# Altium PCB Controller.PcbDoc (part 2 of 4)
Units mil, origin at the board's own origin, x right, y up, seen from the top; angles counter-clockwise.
Board outline 5000 x 8750 mil, 6 copper layers (Top Layer, Layer 1, Layer 2, Layer 3, Layer 4, Bottom Layer), stack 92.6 mil thick; 303 components, 258 nets, 1062 pads, 274 vias.
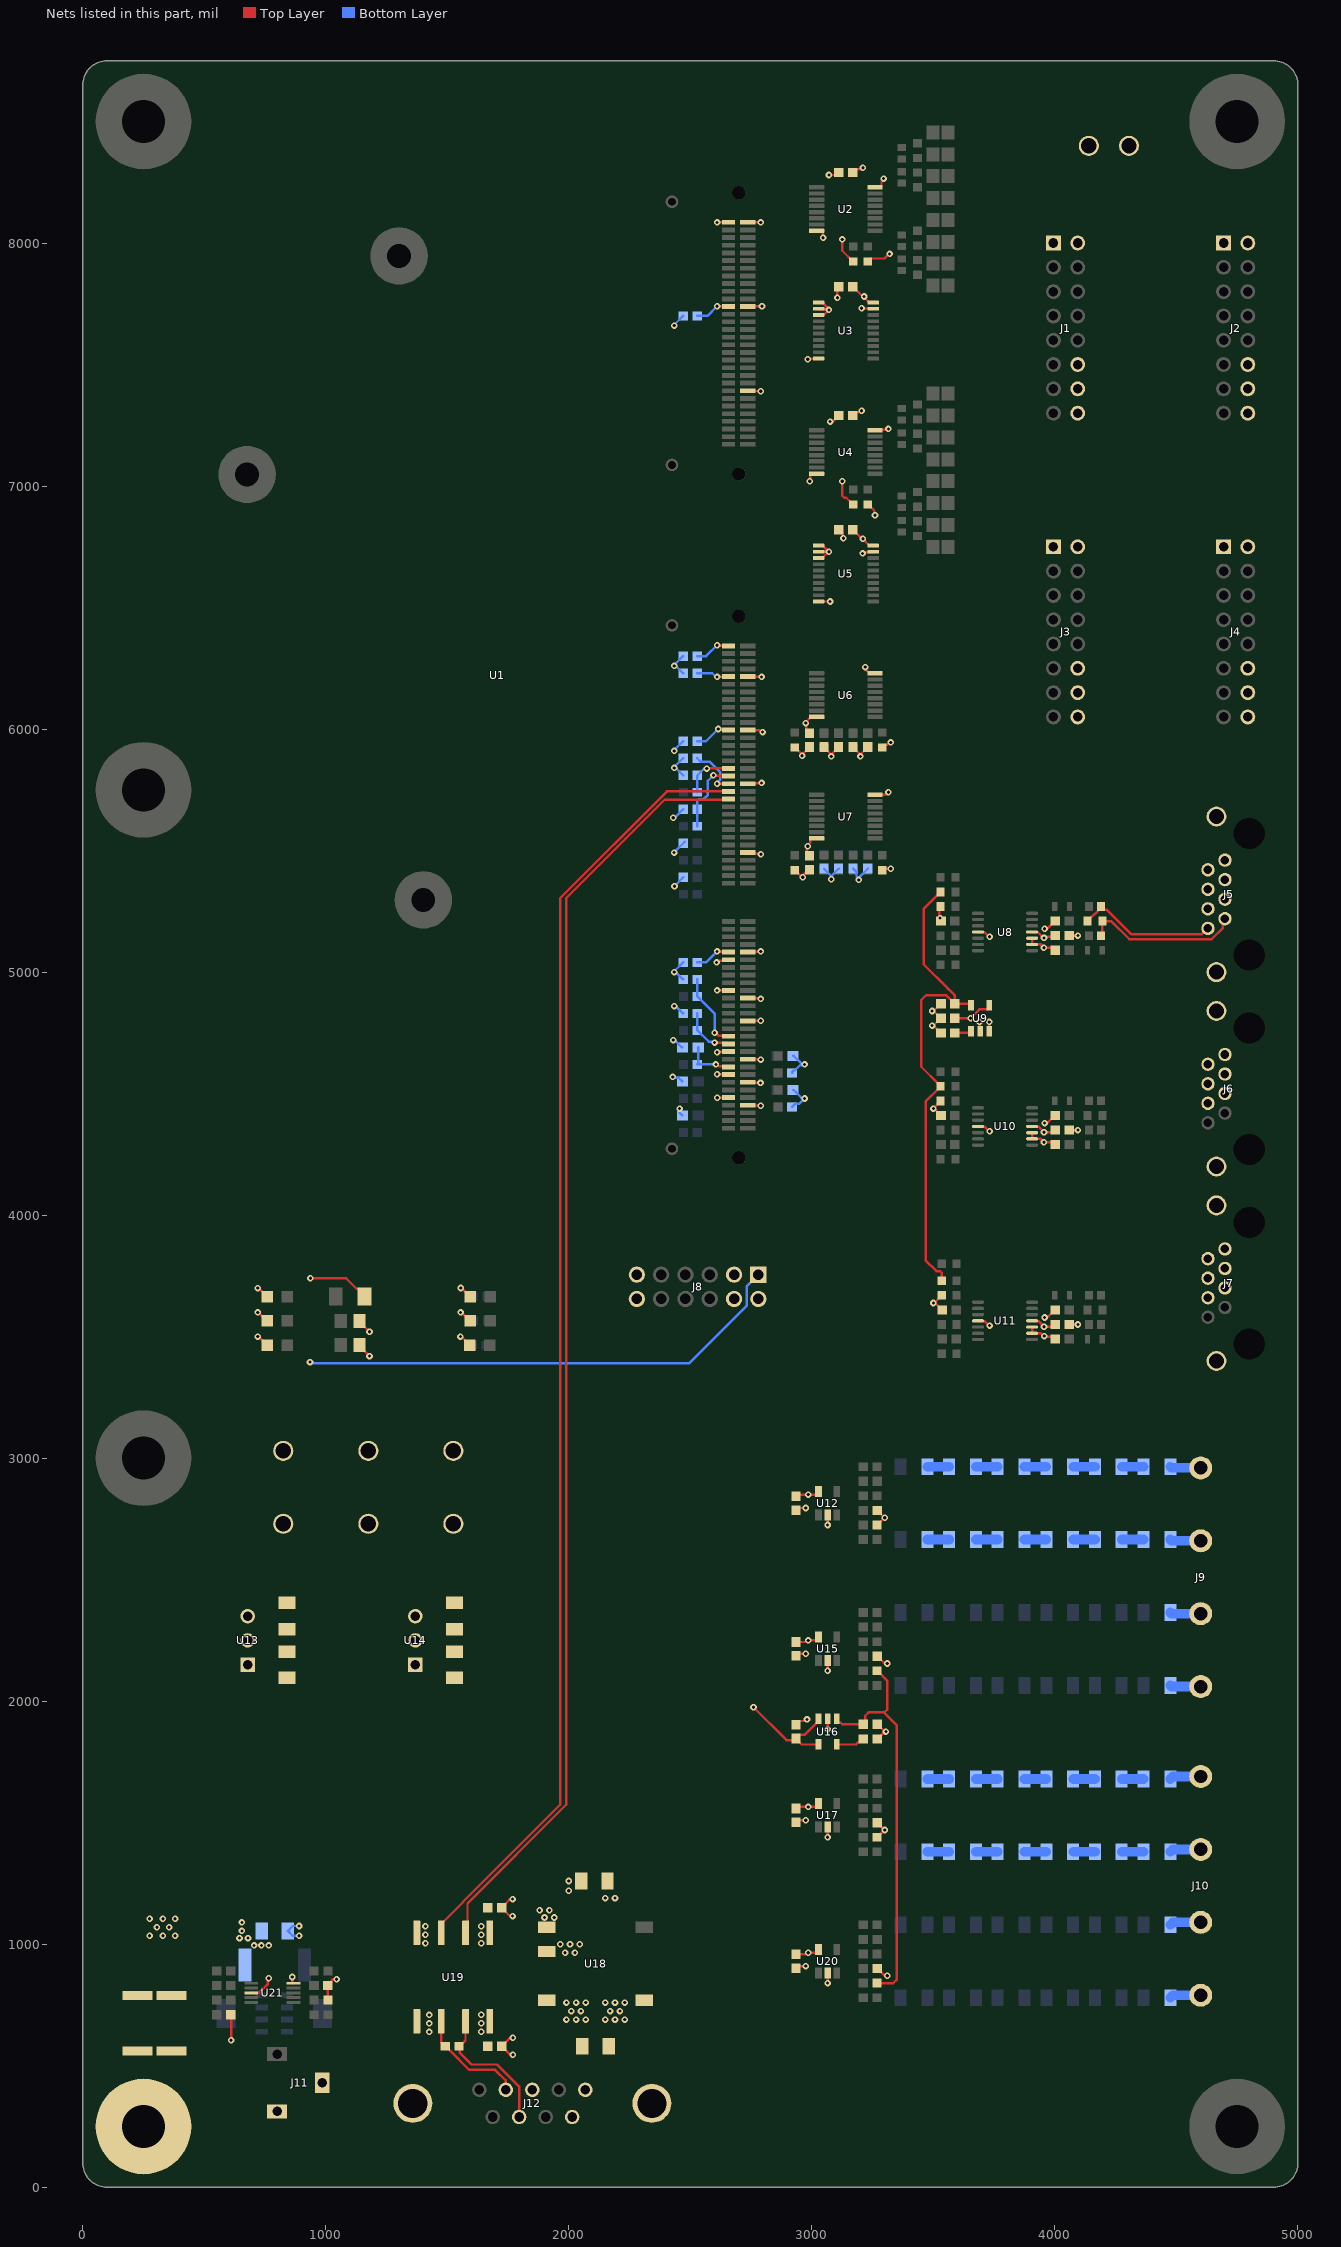
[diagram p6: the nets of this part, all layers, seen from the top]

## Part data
C1 C3 C4 C5 C7 C9 C10 C11: library part CMP-03020-017376-1, "CAP CER 27PF 250V C0G/NP0 0603", Capacitance="27 pF", Case/Package=0603, Manufacturer=KEMET, Package=CBR06C, Temperature="-55°C to +125°C", Temperature Characteristic=C0G, Temperature Coefficient=30ppm/°C, Temperature Range High=+125°C, Temperature Range Low=-55°C, Tolerance=0.01, Voltage Rating=250V
C2 C6 C8 C12 C13 C18 C21 C24 C25 C26 C29 C34 C38 C43 C47 C48 C49 C51 C54 C56 C61 C62 C63 C64 C65 C66 C75: library part CMP-2006-03057-2, "CAP CER 0.1UF 25V X7R 0603", Capacitance=0.10μF, Case/Package=0603, Manufacturer=KEMET, Temperature="-55°C to +125°C", Temperature Characteristic=X7R, Temperature Coefficient=30ppm/°C, Temperature Range High=+125°C, Temperature Range Low=-55°C, Tolerance=0.1, Voltage Rating=25V
C14 C15 C16 C17 C19 C20 C22 C23 C27 C28 C30 C31 C32 C33 C35 C36 C42 C46 C55 C57 C70 C71 C72 C73: library part CMP-001-00096-9, "CAP CER 100PF 50V X7R 0603", Capacitor Type=Ceramic, Case/Package=0603, Manufacturer=YAGEO, Max Operating Temperature=125°C, Min Operating Temperature=-55°C, Temperature Coefficient=X7R, Tolerance=10%, Voltage Rating=50V
C37 C39 C50 C52 C59: "CAP CER 4700PF 25V 10% X7R 0603", Capacitance=4.7nF, Case Code (Imperial)=0603, Case Code (Metric)=1608, Dielectric=X7R, Dielectric Material=Ceramic, Manufacturer=KEMET, Manufacturer Part Number=C0603C472K3RACTU, Max Operating Temperature=125°C, Min Operating Temperature=-55°C, Package Quantity=1, Supplier Part Number 1=67AH9250, Tolerance=10%, Voltage Rating=25V
C40 C41 C44 C45 C53 C60 C85: library part CMP-13271-001434-1, "CAP CER 10UF 25V X7R 1206", Capacitance=10μF, Case Code (Imperial)=1206, Case Code (Metric)=3216, Dielectric=X7R, Manufacturer=SAMSUNG, Max Operating Temperature=125°C, Min Operating Temperature=-55°C, Package Quantity=1, Tolerance=10%, Voltage Rating=25V
C58: "CAP CER 0.022UF 50V X7R 0805", Capacitance=22nF, Case Code (Imperial)=0805, Case Code (Metric)=2012, Dielectric=X7R, Dielectric Material=Ceramic, Insulation Resistance=100GR, Manufacturer=YAGEO, Max Operating Temperature=125°C, Min Operating Temperature=-55°C, Package Quantity=1, Supplier Part Number 1=2104784, Tolerance=10%, Voltage=50V
C67 C68 C69 C74 C76 C77: "CAP CER 56PF 50V C0G/NP0 0603", Capacitance=56pF, Case Code (Imperial)=0603, Case Code (Metric)=1608, Dielectric=C0G, Manufacturer=SAMSUNG, Max Operating Temperature=125°C, Min Operating Temperature=-55°C, Package Quantity=1, Temperature Coefficient=30ppm/°C, Tolerance=5%, Voltage=50V
C78 C79 C81 C82 C84: library part CMP-06035-043171-1, "CAP CER 0.27UF 16V X7R 0603", Capacitance=0.27μF, Case/Package=0603, Dielectric=X7R, Manufacturer=MURATA, Tolerance=10%, Voltage Rating (DC)=16V
C80 C83: library part CMP-001-00098-12, "CAP CER 1000PF 50V C0G/NP0 0603", Capacitor Type=Ceramic, Case/Package=0603, Manufacturer=KEMET, Manufacturer Part Number=C0603C102G5GAC7867, Max Operating Temperature=125°C, Min Operating Temperature=-55°C, Temperature Coefficient=C0G, Tolerance=2%, Voltage Rating=50V
D1 D2 D3 D5: library part CMP-22017-000007-1, "LED GREEN CLEAR CHIP SMD", Case Code (Imperial)=0805, Case Code (Metric)=2012, Color=GREEN, Forward Current=30mA, Forward Voltage=2.1V, Illumination Color=Green, Lens Color=Colorless, Manufacturer=LITE-ON, Max Operating Temperature=85°C, Min Operating Temperature=-55°C, Package Quantity=1, Power Dissipation=100mW, Reverse Voltage=5V, Test Current=10mA
D4: "LED YELLOW CLEAR 0805 SMD", Case Code (Imperial)=0805, Case Code (Metric)=2012, Color=Yellow, Forward Current=30mA, Forward Voltage=2V, Lens Color=Colorless, Manufacturer=LITE-ON, Max Operating Temperature=85°C, Max Power Dissipation=75mW, Min Operating Temperature=-55°C, Package Quantity=1, Reverse Voltage=5V, Supplier Part Number 1=6920950, Test Current=20mA
D6: "LED RED DIFFUSED 0805 SMD", Case Code (Imperial)=0805, Case Code (Metric)=2012, Color=RED, Forward Current=20mA, Forward Voltage=2V, Illumination Color=Red, Manufacturer="VISUAL COMMUNICATIONS", Max Operating Temperature=85°C, Min Operating Temperature=-40°C, Package Quantity=1, Power Rating=100mW, Reverse Voltage=5V, Supplier Part Number 1=45X6246
J1 J2 J3 J4: "CONN HEADER VERT 16POS 2.54MM", Case/Package=N/A, Flammability Rating="UL94 V-0", Insulation Color=Black, Manufacturer=SULLINS, Max Operating Temperature=105°C, Min Operating Temperature=-40°C, Supplier Part Number 1=S9171-ND
J5 J6 J7: "CONN MOD JACK R/A 8P8C SHLD", Case/Package=N/A, Manufacturer=TE
J8: "CONN HEADER VERT 12POS 2.54MM", Case/Package=N/A, Color=Black, Flammability Rating="UL94 V-0", Manufacturer="WURTH ELEKTRONIK", Manufacturer Print=WURTH, Max Operating Temperature=105°C, Min Operating Temperature=-40°C, Supplier Part Number 1=732-5297-ND, Voltage Rating=250V
J9 J10: "TERM BLOCK HDR 4POS 90DEG 7.62MM", Case/Package=N/A, Manufacturer="PHOENIX CONTACT"
J11: "CONN PWR JACK 2X5.5MM SOLDER", Case/Package=N/A, Color=Black, Current Rating=5A, Flammability Rating="UL94 V-0", Insulation Resistance=50MR, Manufacturer=CUI, Manufacturer Print="CUI DEVICES", Max Operating Temperature=85°C, Min Operating Temperature=-25°C, Package Quantity=280, Voltage Rating=24V
J12: "CONN D-SUB PLUG 9POS R/A SLDR", Case/Package=N/A, Color=Black, Current Rating=5A, Manufacturer=AMPHENOL, Max Operating Temperature=155°C, Max Supply Voltage (AC)=250V, Min Operating Temperature=-55°C, Supplier Part Number 1=70145033
L1 L2 L3 L4 L5 L6 L7 L8 L9 L10 L11 L12 L13 L14 L15 L16: library part CMP-08253-000143-1, "FIXED IND 1UH 1.15A 60 MOHM SMD", Case Code (Imperial)=0805, Case Code (Metric)=2012, Current Rating=1.15A, DC Resistance (DCR)=78mR, Inductance=1uH, Manufacturer=TDK, Max Operating Temperature=125°C, Min Operating Temperature=-55°C, Package Quantity=1, Saturation Current=220mA, Self Resonant Frequency=160MHz, Test Frequency=2MHz, Tolerance=20%
Q1 Q2: "MOSFET N-CH 120V 90A PWRDI5060-8", Case/Package=8-PowerTDFN, Manufacturer="DIODES INC", Supplier Part Number 1=68AH9585
R1 R2 R3 R6 R7 R8 R11 R12: library part CMP-009-00005-4, "RES 100 OHM 1% 1/10W 0603", Case/Package=0603, Manufacturer=YAGEO, Manufacturer Part Number=RC0603FR-13100RL, Max Operating Temperature=155°C, Min Operating Temperature=-55°C, Power=0.1W, Tolerance=1%, Voltage Rating=75V
R4 R5 R9 R10 R13 R14 R15 R20: library part CMP-009-00107-4, "RES SMD 15K OHM 0.1% 1/10W 0603", Case/Package=0603, Manufacturer=YAGEO, Max Operating Temperature=155°C, Min Operating Temperature=-55°C, Power=0.1W, Tolerance=0.1%, Voltage Rating=75V
R16 R17 R18 R19 R26 R40 R51 R83 R84 R85 R86: library part CMP-009-00006-5, "RES 120 OHM 1% 1/10W 0603", Case/Package=0603, Manufacturer=YAGEO, Max Operating Temperature=155°C, Min Operating Temperature=-55°C, Power=0.1W, Tolerance=1%, Voltage Rating=75V
R21 R28 R33 R42 R45 R54: library part CMP-009-00218-2, "RES SMD 27K OHM 0.5% 1/16W 0603", Case/Package=0603, Manufacturer=SUSUMU, Max Operating Temperature=125°C, Min Operating Temperature=-55°C, Power=0.06W, Tolerance=0.5%, Voltage Rating=75V
R22 R24 R34 R37 R46 R49: library part CMP-009-00039-5, "RES 20K OHM 1% 1/10W 0603", Case/Package=0603, Manufacturer=STACKPOLE, Max Operating Temperature=155°C, Min Operating Temperature=-55°C, Power=100mW, Tolerance=1%, Voltage Rating=75V
R23 R27 R36 R41 R48 R53: library part CMP-2000-02579-2, "RES SMD 2.7K OHM 0.5% 1/16W 0603", Case Code (Imperial)=0603, Case Code (Metric)=1608, Manufacturer=SUSUMU, Max Operating Temperature=125°C, Max Power Dissipation=63mW, Min Operating Temperature=-55°C, Package Quantity=1, Power Rating=62.5mW, Resistor Type="Thin Film", Temperature Coefficient=25ppm/°C, Tolerance=0.5%, Voltage Rating=75V
R25 R29 R38 R43 R50 R55: library part CMP-009-00255-1, "RES SMD 1K OHM 0.05% 1/10W 0603", Case/Package=0603, Manufacturer=PANASONIC, Max Operating Temperature=155°C, Min Operating Temperature=-55°C, Power=100mW, Temperature Coefficient=10ppm/°C, Tolerance=0.05%, Voltage Rating=75V
R30 R44 R57: library part CMP-009-00206-2, "RES SMD 10K OHM 0.1% 1/10W 0603", Case/Package=0603, Manufacturer=SUSUMU, Manufacturer Part Number=RG1608P-103-B-T5, Max Operating Temperature=155°C, Min Operating Temperature=-55°C, Power=100mW, Tolerance=0.1%, Voltage Rating=75V
R31 R32 R35 R39 R93 R94 R95: "RES SMD 49.9 OHM 1% 1/10W 0603", Case Code (Imperial)=0603, Case Code (Metric)=1608, Manufacturer=PANASONIC, Max Operating Temperature=155°C, Max Power Dissipation=100mW, Min Operating Temperature=-55°C, Package Quantity=5000, Power Rating=0.1W, Resistance=49.9Ω, Resistance Tolerance=1%, Resistor Type="Thick Film", Supplier Part Number 1=12AC1058, Temperature Coefficient=100ppm/°C, Voltage Rating=75V, Voltage Rating (DC)=50V, Working Voltage=6V
R47: "RES 249 OHM 1% 1/4W 1206", Case Code (Imperial)=1206, Case Code (Metric)=3216, Manufacturer=YAGEO, Max Operating Temperature=155°C, Max Power Dissipation=250mW, Min Operating Temperature=-55°C, Power Rating=0.25W, Resistance=249Ω, Resistor Type="Thick Film", Supplier Part Number 1=1142064, Temperature Coefficient=100ppm/°C, Tolerance=1%, Voltage Rating=200V
R52: "RES 499 OHM 1% 1/8W 0805", Case Code (Imperial)=0805, Case Code (Metric)=2012, Manufacturer=YAGEO, Max Operating Temperature=155°C, Max Power Dissipation=0.13W, Min Operating Temperature=-55°C, Package Quantity=1, Power Rating=125mW, Resistance=499Ω, Resistor Type="Thick Film", Supplier Part Number 1=5825161, Temperature Coefficient=100ppm/°C, Tolerance=1%, Voltage Rating=150V
R56: "RES SMD 2.43K OHM 1% 1/8W 0805", Case Code (Imperial)=0805, Case Code (Metric)=2012, Manufacturer=PANASONIC, Max Operating Temperature=155°C, Max Power Dissipation=125mW, Min Operating Temperature=-55°C, Package Quantity=1, Power Rating=0.13W, Resistance=2.43kΩ, Resistance Tolerance=1%, Resistor Type="Thick Film", Supplier Part Number 1=73AC7648, Temperature Coefficient=100ppm/°C, Voltage Rating=150V
R58 R61 R62 R65 R66 R69 R70 R76: "RES 4.99K OHM 1% 1/10W 0603", Case Code (Imperial)=0603, Case Code (Metric)=1608, Manufacturer=YAGEO, Max Operating Temperature=155°C, Max Power Dissipation=0.1W, Min Operating Temperature=-55°C, Package Quantity=1, Resistance=4.99kΩ, Resistance Tolerance=1%, Resistor Type="Thick Film", Supplier Part Number 1=1995595, Temperature Coefficient=100ppm/°C, Voltage Rating=75V, Voltage Rating (DC)=50V
R59 R60 R67 R68: "RES SMD 3.74K OHM 0.1% 1/5W 0603", Case Code (Imperial)=0603, Case Code (Metric)=1608, Manufacturer=PANASONIC, Max Operating Temperature=155°C, Max Power Dissipation=0.2W, Min Operating Temperature=-55°C, Resistance=3.74kΩ, Resistor Type="Thick Film", Temperature Coefficient=50ppm/°C, Tolerance=0.1%
R63 R64 R71 R74: "RES SMD 1.8K OHM 0.1% 1/5W 0603", Case Code (Imperial)=0603, Case Code (Metric)=1608, Manufacturer=PANASONIC, Max Operating Temperature=155°C, Max Power Dissipation=0.2W, Min Operating Temperature=-55°C, Resistance=1.8kΩ, Resistor Type="Thick Film", Temperature Coefficient=50ppm/°C, Tolerance=0.1%
R72 R73: "RES 2.7M OHM 5% 1/10W 0603", Case Code (Imperial)=0603, Case Code (Metric)=1608, Manufacturer=YAGEO, Max Operating Temperature=155°C, Max Power Dissipation=100mW, Min Operating Temperature=-55°C, Package Quantity=1, Power Rating=0.1W, Resistance=2.7MΩ, Resistor Type="Thick Film", Temperature Coefficient=100ppm/°C, Tolerance=5%, Voltage Rating=75V, Voltage Rating (DC)=50V
R75 R81: "RES 100K OHM 1% 1/10W 0603", Case Code (Imperial)=0603, Case Code (Metric)=1608, Manufacturer=YAGEO, Max Operating Temperature=155°C, Max Power Dissipation=100mW, Min Operating Temperature=-55°C, Power Rating=0.1W, Resistance=100kΩ, Resistance Tolerance=1%, Resistor Type="Thick Film", Supplier Part Number 1=3697448, Temperature Coefficient=100ppm/°C, Voltage Rating=50V, Working Voltage=75V
R77 R78: library part CMP-2000-06974-2, "RES SMD 0 OHM JUMPER 1W 2512", Case Code (Imperial)=2512, Case Code (Metric)=6432, Manufacturer=YAGEO, Max Operating Temperature=155°C, Max Power Dissipation=1W, Min Operating Temperature=-55°C, Package Quantity=4000, Resistance Tolerance=5%, Resistor Type="Thick Film", Temperature Coefficient=200ppm/°C, Voltage Rating=200V
R79: library part CMP-2000-00337-2, "RES SMD 22K OHM 1% 1/10W 0603", Case Code (Imperial)=0603, Case Code (Metric)=1608, Manufacturer=PANASONIC, Max Operating Temperature="155 degC", Min Operating Temperature="-55 degC", Package Quantity=200, Power Rating=0.1W, Resistance=22kΩ, Tolerance=1%, Voltage Rating="50 V"
R80: "RES SMD 200K OHM 1% 1/10W 0603", Case Code (Imperial)=0603, Case Code (Metric)=1608, Manufacturer=PANASONIC, Max Operating Temperature=155°C, Max Power Dissipation=0.1W, Min Operating Temperature=-55°C, Package Quantity=1, Power Rating=100mW, Resistance=200kΩ, Resistance Tolerance=1%, Resistor Type="Thick Film", Supplier Part Number 1=25AC9147, Temperature Coefficient=100ppm/°C, Voltage Rating=75V, Voltage Rating (DC)=50V
R82: "RES SMD 120 OHM 5% 1/10W 0603", Case Code (Imperial)=0603, Case Code (Metric)=1608, Manufacturer=YAGEO, Max Operating Temperature=155°C, Max Power Dissipation=0.1W, Min Operating Temperature=-55°C, Package Quantity=1, Power Rating=100mW, Resistance=120Ω, Resistance Tolerance=5%, Resistor Type="Thick Film", Supplier Part Number 1=2424206, Temperature Coefficient=100ppm/°C, Voltage Rating=50V
R87 R88 R89 R90 R91 R92: "RES SMD 0 OHM JUMPER 1/10W 0603", Case Code (Imperial)=0603, Case Code (Metric)=1608, Manufacturer="VISHAY DALE", Manufacturer Part Number=CRCW06030000Z0EBC, Max Operating Temperature=155°C, Max Power Dissipation=100mW, Min Operating Temperature=-55°C, Package Quantity=10000, Ratings=AEC-Q200, Resistance=0Ω, Resistor Type="Thick Film", Supplier Part Number 1=48P7902, Temperature Coefficient=100ppm/°C, Tolerance=1%, Voltage Rating=75V
R96 R97 R98: "RES 680 OHM 1% 1/10W 0603", Case Code (Imperial)=0603, Case Code (Metric)=1608, Manufacturer=YAGEO, Max Operating Temperature=155°C, Max Power Dissipation=100mW, Min Operating Temperature=-55°C, Package Quantity=1, Power Rating=0.1W, Resistance=680Ω, Resistance Tolerance=1%, Resistor Type="Thick Film", Supplier Part Number 1=6789788, Temperature Coefficient=100ppm/°C, Voltage Rating=50V
R99 R100 R101 R102 R103 R104 R105 R106 R107 R108 R109 R110 R111 R112 R113 R114 R115 R116 R117 R118 R119 R120 R121 R122 R123 R124 R125 R126 R127 R128 R129 R130 R131 R132 R133 R134 R135 R136 R137 R138 R139 R140 R142 R143 R144 R145 R146 R147: library part CMP-2003-04604-1, "RES 249K OHM 0.1% 1/4W 1206", Case/Package=1206, Manufacturer="VISHAY DALE", Power=0.25W, Resistance=249kΩ
R141: "RES 0.01 OHM 1% 2W 2512", Case Code (Imperial)=2512, Case Code (Metric)=6432, Manufacturer=YAGEO, Max Operating Temperature=170°C, Max Power Dissipation=2W, Min Operating Temperature=-55°C, Resistance=10mΩ, Resistor Type="Metal Film", Supplier Part Number 1=1995902P, Temperature Coefficient=50ppm/°C, Tolerance=1%
TP1 TP2 TP6 TP7 TP8: library part CMP-1672-00003-4, "PC TEST POINT MULTIPURPOSE BLACK", Case/Package=N/A, Colour=Black, Manufacturer=KEYSTONE, Package Quantity=100
TP3 TP4 TP5: library part CMP-1672-00002-4, "PC TEST POINT MULTIPURPOSE RED", Case/Package=N/A, Colour=Red, Manufacturer=KEYSTONE, Package Quantity=100
U1: "CONTROLCARD TMS320F28379D EVAL", Case/Package=N/A, Manufacturer="TEXAS INSTRUMENTS", Supplier Part Number 1=595-TMDSCNCD28379D
U2 U4: library part CMP-0310-00537-3, "IC RECEIVER 0/4 16TSSOP", Case/Package=16-TSSOP, Manufacturer="TEXAS INSTRUMENTS", Rating=Catalog, Receivers Per Package=4, Supply Voltage(s)(Max)(V)=3.6, Supply Voltage(s)(Min)(V)=3, Supply Voltage(s)(V)=3.3
U3 U5: library part CMP-0440-01163-3, "IC BUF NON-INVERT 5.5V 20TSSOP", Case/Package=20-TSSOP, F @ Nom Voltage(Max)(Mhz)=110, Generic Part Number=SN74LV541AT, ICC @ Nom Voltage(Max)(mA)=0.02, Manufacturer="TEXAS INSTRUMENTS", Operating Temperature Range(C)="-40 to 125", Rating=Catalog, tpd @ Nom Voltage(Max)(ns)=7.9, Voltage(Nom)(V)=5
U6 U7: library part CMP-0310-00542-2, Case/Package=16-TSSOP, Drivers Per Package=4, Manufacturer="TEXAS INSTRUMENTS", Rating=Catalog, Supply Voltage(s)(Max)(V)=3.6, Supply Voltage(s)(Min)(V)=3, Supply Voltage(s)(V)=3.3
U8 U10 U11: library part CMP-0384-01836-1, "IC CMOS 4 CIRCUIT 14TSSOP", Amplifiers Per Package=4, Case/Package=14-TSSOP, Generic Part Number=AD8618, Input Bias Current=200fA, Input Offset Voltage=23uV, Manufacturer="ANALOG DEVICES"
U9 U16: library part CMP-04916-000006-1, "IC VREF SERIES 1.5V/3V 5SOT", Case/Package=TSOT-23-5, Manufacturer="TEXAS INSTRUMENTS", Max Junction Temp=+150°C, Max Supply Voltage=5.5V, Min Supply Voltage=3V, Nominal Supply Current=360uA, Output Voltage=1.5/3V, Package=DDC0005A, Temperature="-40°C to +125°C", Temperature Range High=+125°C, Temperature Range Low=-40°C
U12 U15 U17 U20: library part CMP-0384-02059-2, "IC OPAMP GP 1 CIRCUIT TSOT23-5", Amplifiers Per Package=1, Case/Package=TSOT-23-5, Generic Part Number=AD8615, Input Bias Current=200fA, Input Offset Voltage=80uV, Manufacturer="ANALOG DEVICES"
U13: "DC DC CONVERTER 3.3V 3W", Case/Package=SIP, Manufacturer=RECOM, Max Input Voltage=28V, Max Operating Temperature=85°C, Max Output Current=1A, Max Output Power=3.3W, Max Output Voltage=3.3V, Max Power Dissipation=3W, Min Input Voltage=8V, Min Input Voltage (DC)=7V, Min Operating Temperature=-40°C, Package=3-SIP, Supplier Part Number 1=9176626
U14: "DC DC CONVERTER 5V 5W", Case/Package=SIP, Current - Output 1=1A, Manufacturer=RECOM, Max Input Voltage=28V, Max Operating Temperature=85°C, Max Output Voltage=5V, Max Power Dissipation=5W, Min Input Voltage=8V, Min Operating Temperature=-40°C, Package=3-SIP, Package Quantity=42, Supplier Part Number 1=1446013
U18: "DC DC CONVERTER 5V 1W", Case/Package=SMD/SMT, Current - Output 1=200mA, Isolation Voltage=2kV, Manufacturer=RECOM, Max Input Voltage=3.63V, Max Operating Temperature=100°C, Max Output Power=1W, Max Output Voltage=5V, Min Input Voltage=2.97V, Min Operating Temperature=-40°C, Package=8-SMD, Supplier Part Number 1=945-R1SE-3.305/H2-RCT-ND
U19: "IC TXRX/ISO HALF 1/1 8SOP", Case/Package=8-SOP, Drivers Per Package=1, Manufacturer="TEXAS INSTRUMENTS", Rating=Catalog
U21: "IC SURGE SUPPRESSION ADJ 10MSOP", Case/Package=10-MSOP, Manufacturer="ANALOG DEVICES", Supplier Part Number 1=505-LTC4368IMS-2#PBF-ND

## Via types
v1: diameter 27, hole 13, Top Layer to Bottom Layer, tented both sides, 274 vias

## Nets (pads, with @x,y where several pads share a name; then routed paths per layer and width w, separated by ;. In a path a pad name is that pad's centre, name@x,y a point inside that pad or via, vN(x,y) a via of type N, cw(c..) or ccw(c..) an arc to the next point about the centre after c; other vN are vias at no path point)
+1.5V_I: C26.1 U9.1 | length 69.5
  Top Layer w10: C26.1@3588.58,4750 3648.39,4750 U9.1@3655.2,4756.81
+1.5V_V: C47.1 R64.2 R74.2 U16.1 | length 1646.7
  Top Layer w10: U16.1@3102.4,1928.15 3102.4,1918.31 3109.21,1911.5 3119.06,1911.5 3125.55,1905 3205.95,1905 3219.81,1918.86 3219.81,1939.81 3235,1955 3295,1955 3350,1900 3350,855 3335,840 R74.2@3268.62,840 ; R64.2@3268.62,2125 3269.53,2125 3310,2084.53 3310,1965 3297.5,1952.5
+3.3V: C2.1 C6.1 C8.1 C12.1 C13.1 C18.1 C38.1 C40.1 C43.1 C51.1 C53.1 C54.1 C56.1 J8.1 R4.2 R9.2 R14.2 R20.2 R47.1 TP3.1 U2.16 U3.20 U4.16 U5.20 U6.16 U7.16 U12.5 U13.3 U15.5 U17.5 U18.2 U19.1 U20.5 | length 3676.5
  Top Layer w10: v1(936.54,3740) 1084.1,3740 1127.52,3696.58 1135.45,3696.58 1159.1,3672.92 R47.1@1159.1,3665 ; C56.1@2935,958.58 2973.98,958.58 2980.4,965 v1(2985,965) 3018.82,965 3027.6,973.78 U20.5@3027.6,978.23 ; C51.1@2935,1558.58 2941.42,1565 v1(2985,1565) 3018.82,1565 3027.6,1573.78 U17.5@3027.6,1578.23 ; C43.1@2935,2243.58 2973.98,2243.58 2980.4,2250 v1(2985,2250) 3018.82,2250 3027.6,2258.78 U15.5@3027.6,2263.23 ; C38.1@2935,2843.58 2941.42,2850 3018.82,2850 3027.6,2858.78 U12.5@3027.6,2863.23 ; v1(2983.41,5518.1) v1@2978.25,5518.1 ; C18.1@2990,5483.58 2978.25,5495.32 v1@2978.25,5518.1 ; C13.1@2990,5983.58 2976.14,5997.44 2976.14,6023.86 2975,6025 2975,6028.15 2997.28,6050.43 U6.16@3019.92,6050.43 ; U7.16@3019.92,5550.43 2997.28,5550.43 2993.43,5546.57 2993.43,5532.72 2978.81,5518.1 v1@2978.25,5518.1 ; v1(3125,7020) 3125,6960 3133.25,6951.75 3141.62,6951.75 3168.95,6924.42 R9.2@3170,6924.42 ; v1(3125,8015) 3125,7968.37 3168.95,7924.42 R4.2@3170,7924.42 ; C12.1@3168.58,6820 3169.53,6820 3206.22,6783.31 v1(3210,6783.31) 3210,6781.61 3236.46,6755.16 U5.20@3252.2,6755.16 ; C8.1@3168.58,7290 3182.44,7303.86 3194.26,7303.86 3200.4,7310 v1(3205,7310) ; C6.1@3168.58,7820 3169.53,7820 3206.27,7783.25 3211.75,7783.25 v1(3215,7780) 3215,7776.61 3236.46,7755.16 U3.20@3252.2,7755.16 ; C2.1@3168.58,8290 3182.44,8303.86 3199.26,8303.86 3205.4,8310 v1(3210,8310) ; U4.16@3260.08,7229.57 3262.8,7232.28 3312.28,7232.28 v1(3315,7235) ; U2.16@3260.08,8229.57 3282.72,8229.57 3286.57,8233.43 3286.57,8251.97 3295,8260.4 v1(3295,8265) ; R20.2@3290,5424.42 3290.58,5425 v1(3325,5425) ; R14.2@3290,5924.42 3301.9,5936.32 3311.42,5936.32 3320.37,5945.27 v1(3324.97,5945.27)
  Bottom Layer w10: v1(935,3395) 938.25,3391.75 947.61,3391.75 949.36,3390 2495,3390 2731.54,3626.54 2731.54,3706.54 J8.1@2780,3755
  other v1: 1985,965 2025,965 1965,1000 2005,1000 2045,1000 1640,1004.17 1640,1039.17 1640,1074.17 2150,1190 2190,1190 2985,2850 2975.15,6024.85
+3V_I: C24.1 R22.2 R34.2 R46.2 U9.5 | length 2017.5
  Top Layer w10: R22.2@3529.42,5330 3529.42,5328.95 3460,5259.53 3460,5032.09 3559.9,4932.19 3560.25,4932.19 3588.58,4903.86 C24.1@3588.58,4870 ; R46.2@3534.42,3730 3534.42,3762.96 3527.83,3769.54 3512.34,3769.54 3468,3813.88 3468,4467.53 3522.74,4522.26 3522.74,4537.74 3450,4610.47 3450,4885 3470,4905 3552.78,4905 3563.74,4894.04 3563.74,4893.89 3587.63,4870 C24.1@3588.58,4870 ; U9.5@3655.2,4863.19 3648.39,4870 C24.1@3588.58,4870
+3V_V: C49.1 U16.5 | length 113.6
  Top Layer w10: U16.5@3102.4,1821.85 3182.32,1821.85 3205.47,1845 C49.1@3206.42,1845
+5V: C21.1 C25.1 C29.1 C34.1 C41.1 C48.1 C62.1 C63.1 C64.1 C65.1 C66.1 C75.1 J5.2 J5.5 J5.6 J6.2 J6.5 J6.6 J7.2 J7.5 J7.6 J8.2 R52.2 TP4.1 U1.48 U1.84 U1.98 U1.112 U1.120 U1.158 U1.180 U8.4 U9.3 U9.4 U10.4 U11.4 U14.3 U16.3 U16.4 | length 2054.8
  Top Layer w10: R52.2@1138.46,3565 1138.46,3560.98 1179.45,3520 v1(1180,3520) ; v1(2610,5085) 2611.36,5083.64 2656.32,5083.64 U1.48@2657.68,5082.28 ; v1(2610,5775) 2610.1,5775.1 2657.58,5775.1 U1.84@2657.68,5775.2 ; v1(2610,6215) 2610.57,6215.57 2657.11,6215.57 U1.112@2657.68,6216.14 ; v1(2610,6345) 2611.44,6343.56 2656.24,6343.56 U1.120@2657.68,6342.13 ; v1(2610,7740) 2610.65,7739.35 2657.03,7739.35 U1.158@2657.68,7738.71 ; v1(2610,8085) 2610.08,8085.08 2657.59,8085.08 U1.180@2657.68,8085.17 ; v1(2614.84,6000.36) 2617.19,5998.01 2650.76,5998.01 2653.05,6000.3 U1.98@2657.68,5995.67 ; v1(2760,1975) 2895,1840 2928.58,1840 C48.1@2935,1846.42 ; U16.4@3027.6,1821.85 2958.62,1821.85 2935,1845.47 C48.1@2935,1846.42 ; U16.3@3027.6,1928.15 3027.6,1918.31 2970.53,1861.24 2948.86,1861.24 2935,1847.37 C48.1@2935,1846.42 ; C25.1@3588.58,4810 v1(3653.19,4810) 3689.69,4846.5 3723.19,4846.5 3730,4853.31 U9.4@3730,4863.15 ; U9.3@3730,4756.85 v1(3730,4795) ; U11.4@3906.22,3565 3906.94,3564.28 3931.96,3564.28 v1(3955.21,3541.03) 3992.46,3541.03 C34.1@4001.42,3550 ; U10.4@3906.22,4365 3906.94,4364.28 3931.96,4364.28 v1(3955.21,4341.03) 3992.46,4341.03 C29.1@4001.42,4350 ; U8.4@3906.22,5165 3906.94,5164.28 3930.42,5164.28 3953.66,5141.03 v1(3955.21,5141.03) ; v1@3955.4,5145 3986.42,5145 C21.1@3991.42,5150
  Bottom Layer w10: C75.1@2528.58,5040 2565,5040 v1(2610,5085) ; C66.1@2528.58,5880 2542.44,5866.14 2578.86,5866.14 2609.85,5835.15 2610.15,5835.15 2623.5,5821.81 2623.5,5793.1 2610,5779.6 v1(2610,5775) ; C65.1@2528.58,5950 2564.48,5950 v1(2614.84,6000.36) ; C64.1@2528.58,6230 2590.4,6230 2605.4,6215 v1(2610,6215) ; C63.1@2528.58,6300 2565,6300 v1(2610,6345) ; C62.1@2528.58,7700 2570,7700 v1(2610,7740)
+5V_ISO: C60.1 C61.1 J12.9 U18.5 U19.8
  other v1: 1640,640 1640,675 2150,690 2190,690 2230,690 1640,710 2170,725 2210,725 2150,760 2190,760 2230,760
+12V: C44.1 C45.1 C85.1 J1.1 J2.1 J3.1 J4.1 J8.12 R56.2 R141.2 TP5.1 U13.1 U14.1 U21.8 | length 171.1
  Top Layer w10: U21.8@692.91,800 693.82,800.91 725.77,800.91 761.75,836.88 761.75,856.75 v1(765,860) ; R56.2@1138.46,3465 1138.46,3460.98 1179.45,3420 v1(1180,3420)
  other v1: 705,995 735,995 765,995 645,1025 680,1025 655,1055 655,1090
AC+_IN: J10.1 R142.1 | length 129
  Bottom Layer w40: R142.1@4475.12,780 4485.12,790 J10.1@4600,790
AC+_OUT: J9.1 R117.1 | length 127
  Bottom Layer w40: R117.1@4475.12,2065 4480.12,2060 J9.1@4600,2060
AC-_IN: J10.2 R135.1 | length 129
  Bottom Layer w40: R135.1@4475.12,1080 4485.12,1090 J10.2@4600,1090
AC-_OUT: J9.2 R111.1 | length 127
  Bottom Layer w40: R111.1@4475.12,2365 4480.12,2360 J9.2@4600,2360
ADC_B4: C77.1 R92.2 U1.24 | length 222.1
  Top Layer w10: v1(2600,4710) 2628.5,4710 2629.33,4709.17 2652.83,4709.17 U1.24@2657.68,4704.33
  Bottom Layer w10: C77.1@2528.58,4830 C77.1@2528.58,4830 R92.2@2528.62,4760 2529.53,4760 2576.27,4713.25 2596.75,4713.25 v1(2600,4710)
ADC_B5: C76.1 R91.2 U1.26 | length 313.5
  Top Layer w10: v1(2600.15,4750.15) 2604.45,4750.15 2616.1,4738.5 2655.01,4738.5 U1.26@2657.68,4735.83
  Bottom Layer w10: C76.1@2528.58,4970 C76.1@2528.58,4970 R91.2@2528.62,4900 2529.53,4900 2600.15,4829.38 v1(2600.15,4750.15)
CAN_H: J12.7 R82.2 U19.7 | length 567.6
  Top Layer w10: R82.2@1548.62,580 1552.1,576.52 1552.1,552.9 1600,505 1705,505 1795.47,414.53 J12.7@1795.47,289.09 ; R82.2@1550.91,580 1575,604.09 U19.7@1575,682.91
CAN_L: J12.2 R82.1 U19.6 | length 455.8
  Top Layer w10: U19.6@1475,682.91 1475,596.85 1504.81,567.04 1506.75,567.04 1512.61,561.19 1512.61,560.7 1590.22,483.09 1696.91,483.09 1740.27,439.73 1740.27,401.58 J12.2@1740.94,400.91
CAN_RX: U1.80 U19.2 | length 5266.2
  Top Layer w10: U19.2@1575,1047.09 1583.07,1055.16 1583.07,1168.07 1989.04,1574.04 1989.04,5304.04 2395,5710 2655.47,5710 U1.80@2657.68,5712.2
CAN_TX: U1.82 U19.3 | length 5335.3
  Top Layer w10: U19.3@1475,1047.09 1475,1083.5 1565.57,1174.08 1565.57,1175.32 1965,1574.75 1965,5305 2403.7,5743.7 U1.82@2657.68,5743.7
DC+_IN: J10.3 R129.1 | length 129
  Bottom Layer w40: R129.1@4475.12,1380 4485.12,1390 J10.3@4600,1390
DC+_OUT: J9.3 R105.1 | length 127
  Bottom Layer w40: R105.1@4475.12,2665 4480.12,2660 J9.3@4600,2660
DC+I1: R129.2 R130.1 | length 89.8
  Bottom Layer w40: R130.1@4275.12,1380 R129.2@4364.88,1380
DC+I2: R130.2 R131.1 | length 89.8
  Bottom Layer w40: R131.1@4075.12,1380 R130.2@4164.88,1380
DC+I3: R131.2 R132.1 | length 89.8
  Bottom Layer w40: R132.1@3875.12,1380 R131.2@3964.88,1380
DC+I4: R132.2 R133.1 | length 89.8
  Bottom Layer w40: R133.1@3675.12,1380 R132.2@3764.88,1380
DC+I5: R133.2 R134.1 | length 89.8
  Bottom Layer w40: R134.1@3475.12,1380 R133.2@3564.88,1380
DC+O1: R105.2 R106.1 | length 89.8
  Bottom Layer w40: R106.1@4275.12,2665 R105.2@4364.88,2665
DC+O2: R106.2 R107.1 | length 89.8
  Bottom Layer w40: R107.1@4075.12,2665 R106.2@4164.88,2665
DC+O3: R107.2 R108.1 | length 89.8
  Bottom Layer w40: R108.1@3875.12,2665 R107.2@3964.88,2665
DC+O4: R108.2 R109.1 | length 89.8
  Bottom Layer w40: R109.1@3675.12,2665 R108.2@3764.88,2665
DC+O5: R109.2 R110.1 | length 89.8
  Bottom Layer w40: R110.1@3475.12,2665 R109.2@3564.88,2665
DC-_IN: J10.4 R123.1 | length 129
  Bottom Layer w40: R123.1@4475.12,1680 4485.12,1690 J10.4@4600,1690
DC-_OUT: J9.4 R99.1 | length 127
  Bottom Layer w40: R99.1@4475.12,2965 4480.12,2960 J9.4@4600,2960
DC-I1: R123.2 R124.1 | length 89.8
  Bottom Layer w40: R124.1@4275.12,1680 R123.2@4364.88,1680
DC-I2: R124.2 R125.1 | length 89.8
  Bottom Layer w40: R125.1@4075.12,1680 R124.2@4164.88,1680
DC-I3: R125.2 R126.1 | length 89.8
  Bottom Layer w40: R126.1@3875.12,1680 R125.2@3964.88,1680
DC-I4: R126.2 R127.1 | length 89.8
  Bottom Layer w40: R127.1@3675.12,1680 R126.2@3764.88,1680
DC-I5: R127.2 R128.1 | length 89.8
  Bottom Layer w40: R128.1@3475.12,1680 R127.2@3564.88,1680
DC-O1: R99.2 R100.1 | length 89.8
  Bottom Layer w40: R100.1@4275.12,2965 R99.2@4364.88,2965
DC-O2: R100.2 R101.1 | length 89.8
  Bottom Layer w40: R101.1@4075.12,2965 R100.2@4164.88,2965
DC-O3: R101.2 R102.1 | length 89.8
  Bottom Layer w40: R102.1@3875.12,2965 R101.2@3964.88,2965
DC-O4: R102.2 R103.1 | length 89.8
  Bottom Layer w40: R103.1@3675.12,2965 R102.2@3764.88,2965
DC-O5: R103.2 R104.1 | length 89.8
  Bottom Layer w40: R104.1@3475.12,2965 R103.2@3564.88,2965
EGND: MH5.1 R77.2 R78.2
GND: C2.2 C6.2 C8.2 C12.2 C13.2 C14.2 C15.2 C16.2 C17.2 C18.2 C19.2 C20.2 C21.2 C23.2 C24.2 C25.2 C26.2 C27.2 C28.2 C29.2 C31.2 C32.2 C33.2 C34.2 C36.2 C38.2 C39.2 C40.2 C41.2 C43.2 C44.2 C45.2 C46.2 C47.2 C48.2 C49.2 C51.2 C52.2 C53.2 C54.2 C56.2 C57.2 C58.2 C59.2 C62.2 C63.2 C64.2 C65.2 C66.2 C67.2 C68.2 C69.2 C70.2 C71.2 C72.2 C73.2 C74.2 C75.2 C76.2 C77.2 C78.2 C79.2 C80.2 C81.2 C82.2 C83.2 C84.2 C85.2 D1.1 D2.1 D3.1 D4.1 D5.1 D6.1 J1.2 J1.12 J1.14 J1.16 J2.2 J2.12 J2.14 J2.16 J3.2 J3.12 J3.14 J3.16 J4.2 J4.12 J4.14 J4.16 J5.1 J5.3 J5.4 J5.9 J5.10 J6.1 J6.3 J6.4 J6.9 J6.10 J7.1 J7.3 J7.4 J7.9 J7.10 J8.3 J8.4 J8.11 J11.2 J11.3 R5.1 R10.1 R13.1 R15.1 R24.1 R37.1 R49.1 R60.1 R68.1 R77.1 R78.1 R80.1 TP1.1 TP2.1 TP6.1 TP7.1 TP8.1 U1.7 U1.10 U1.13 U1.16 U1.19 U1.22 U1.29 U1.35 U1.38 U1.46 U1.47 U1.65 U1.83 U1.97 U1.111 U1.135 U1.157 U1.179 U2.8 U3.1 U3.2 U3.3 U3.10 U3.19 U4.8 U5.1 U5.2 U5.3 U5.10 U5.19 U6.8 U7.8 U8.2 U8.3 U8.11 U9.2 U10.2 U10.3 U10.11 U11.2 U11.3 U11.11 U12.2 U13.2 U14.2 U15.2 U16.2 U17.2 U18.1 U19.4 U20.2 U21.5 | length 6632.3
  Top Layer w10: C59.2@607.24,710 610.15,707.09 v1(610.15,605.15) ; v1(720,3500) 723.66,3500 D5.1@758.66,3465 ; v1(720,3600) 723.66,3600 D3.1@758.66,3565 ; v1(720,3700) 723.66,3700 D1.1@758.66,3665 ; v1(861.89,865) 861.89,840.28 862.8,839.37 U21.5@867.09,839.37 ; R80.1@1009.53,770 R80.1@1008.62,770 C58.2@1008.58,830 C58.2@1008.58,830 1009.53,830 1023.39,843.86 1023.39,851.15 1028.22,855.98 v1(1044.63,855.98) ; v1(1553.66,3500) 1557.32,3500 D6.1@1592.32,3465 ; v1(1555,3600) 1558.66,3600 D4.1@1593.66,3565 ; v1(1555.15,3700.15) 1558.51,3700.15 D2.1@1593.66,3665 ; v1(1768.58,1115.47) 1765.32,1118.73 1754.85,1118.73 C54.2@1723.58,1150 1723.58,1150.94 1754.85,1182.22 1765.32,1182.22 v1(1768.58,1185.47) ; v1(2608.32,5040) 2612.92,5040 2618.86,5045.94 2652.83,5045.94 U1.46@2657.68,5050.79 ; v1(2610,4580) 2610.83,4579.17 2656.85,4579.17 U1.16@2657.68,4578.35 ; v1(2610,4670) 2611.42,4671.42 2656.26,4671.42 U1.22@2657.68,4672.83 ; v1(2610,4925) 2610.1,4924.9 2657.58,4924.9 U1.38@2657.68,4924.8 ; v1(2610.59,4483) 2611.02,4483.43 2657.25,4483.43 U1.10@2657.68,4483.86 ; U1.7@2736.42,4452.36 2737.6,4451.18 2788.82,4451.18 v1(2790,4450) ; U1.13@2736.42,4546.85 2737.92,4545.34 2787.33,4545.34 v1(2788.84,4543.84) ; U1.19@2736.42,4641.34 2737.09,4640.67 2789.33,4640.67 v1(2790,4640) ; U1.29@2736.42,4798.82 2737.01,4799.41 2789.41,4799.41 v1(2790,4800) ; U1.35@2736.42,4893.31 2738.07,4891.65 2788.35,4891.65 v1(2790,4890) ; U1.47@2736.42,5082.28 2737.78,5083.64 2788.64,5083.64 v1(2790,5085) ; U1.65@2736.42,5491.73 2740.05,5488.1 2786.9,5488.1 v1(2790.15,5484.85) ; U1.83@2736.42,5775.2 2738.05,5776.83 2791.87,5776.83 v1(2793.5,5778.46) ; U1.97@2736.42,5995.67 2736.75,5995.33 2785.07,5995.33 2793.05,5987.35 v1(2797.65,5987.35) ; U1.111@2736.42,6216.14 2736.99,6215.57 2792.93,6215.57 v1(2793.5,6215) ; U1.135@2736.42,7392.25 2737.54,7391.13 2788.87,7391.13 v1(2790,7390) ; U1.157@2736.42,7738.71 2737.06,7739.35 2794.35,7739.35 v1(2795,7740) ; U1.179@2736.42,8085.17 2736.5,8085.08 2789.92,8085.08 v1(2790,8085) ; R15.1@2930,5419.42 2931.05,5419.42 2960.47,5390 v1(2962.74,5390) 2965.99,5393.25 2965.99,5401.46 2979.53,5415 2990,5415 C18.2@2990,5426.42 ; R13.1@2930,5924.42 2931.05,5924.42 2956.75,5898.73 2956.75,5893.25 v1(2960,5890) 2963.25,5893.25 2963.25,5898.73 2990,5925.47 C13.2@2990,5926.42 ; C56.2@2935,901.42 2943.58,910 v1(2975,910) ; C51.2@2935,1501.42 2943.58,1510 v1(2975,1510) ; C48.2@2935,1903.58 2935,1904.53 2948.86,1918.39 2968.79,1918.39 2975.4,1925 v1(2980,1925) ; C43.2@2935,2186.42 2943.58,2195 v1(2975,2195) ; C38.2@2935,2786.42 2943.58,2795 v1(2975,2795) ; v1(2983.5,7522.01) 2984.92,7523.43 3026.38,7523.43 U3.10@3027.8,7524.84 ; v1(2991.42,7019.85) 2993.43,7021.85 2993.43,7046.57 2997.28,7050.43 U4.8@3019.92,7050.43 ; U2.8@3019.92,8050.43 3041.63,8050.43 3045.48,8046.57 3045.48,8022.52 v1(3046.5,8021.5) ; U5.10@3027.8,6524.84 3027.87,6524.92 3074.92,6524.92 v1(3075,6525) ; U5.3@3027.8,6703.98 3033.98,6703.98 3035,6705 3044.57,6705 v1@3069.35,6729.78 ; U5.2@3027.8,6729.57 3028.01,6729.78 v1@3069.35,6729.78 ; U5.1@3027.8,6755.16 3043.54,6755.16 3068.7,6730 v1@3069.57,6730 ; U3.3@3027.8,7703.98 3030.67,7706.85 3051.85,7706.85 v1(3070,7725) ; U3.2@3027.8,7729.57 3030.08,7727.28 3067.72,7727.28 v1(3070,7725) ; U3.1@3027.8,7755.16 3043.54,7755.16 3070,7728.7 v1(3070,7725) ; C14.2@3050,5926.42 3050,5925.47 3076.75,5898.73 3076.75,5890.59 v1(3080,5887.34) 3083.25,5890.59 3083.25,5898.73 3110,5925.47 C15.2@3110,5926.42 ; v1(3065,840) U20.2@3065,881.77 ; v1(3065,1440) U17.2@3065,1481.77 ; v1(3065,1885) U16.2@3065,1928.15 ; v1(3065,2125) U15.2@3065,2166.77 ; v1(3065,2725) U12.2@3065,2766.77 ; v1(3070,6730) 3069.78,6729.78 v1@3069.35,6729.78 ; v1(3070,8280) 3101.42,8280 C2.2@3111.42,8290 ; v1(3075,7265) 3078.25,7268.25 3088.73,7268.25 3110.47,7290 C8.2@3111.42,7290 ; v1(3105,7775) 3105,7813.58 C6.2@3111.42,7820 ; C12.2@3111.42,6820 3112.37,6820 3126.24,6806.14 3126.24,6793.36 3130,6789.6 v1(3130,6785) ; C16.2@3170,5926.42 3170,5925.47 3196.75,5898.73 3196.75,5890.59 v1(3200,5887.34) 3203.25,5890.59 3203.25,5898.73 3230,5925.47 C17.2@3230,5926.42 ; v1(3205,7731.69) 3206.06,7730.63 3251.14,7730.63 U3.19@3252.2,7729.57 ; v1(3208.81,6723.15) 3213.41,6723.15 3217.11,6726.85 3249.49,6726.85 U5.19@3252.2,6729.57 ; v1(3220,6255) 3223.25,6251.75 3223.25,6243.76 3237.44,6229.57 U6.8@3260.08,6229.57 ; R10.1@3230,6924.42 3231.05,6924.42 3257.1,6898.37 3257.1,6882.9 v1(3260,6880) ; R5.1@3230,7924.42 3241.9,7936.32 3298.37,7936.32 3317.05,7955 v1(3320,7955) ; U7.8@3260.08,5729.57 3301.29,5729.57 3311.72,5740 v1(3315,5740) ; C57.2@3268.58,900 3269.53,900 3296.27,873.25 3306.75,873.25 v1(3310,870) ; R68.1@3268.62,1440 3269.53,1440 v1@3299.53,1470 ; C52.2@3268.58,1500 3269.53,1500 v1@3299.53,1470 ; C49.2@3268.58,1845 3269.53,1845 3296.27,1871.75 3301.75,1871.75 v1(3305,1875) 3301.75,1878.25 3296.27,1878.25 3269.53,1905 C47.2@3268.58,1905 ; C46.2@3268.58,2185 3269.53,2185 3296.27,2158.25 3306.75,2158.25 v1(3310,2155) ; R60.1@3268.62,2725 3269.53,2725 v1@3299.53,2755 ; C39.2@3268.58,2785 3269.53,2785 v1@3299.53,2755 ; v1(3300,1470) v1@3299.53,1470 ; v1(3300,2755) v1@3299.53,2755 ; v1(3495,4840) 3498.25,4836.75 3503.73,4836.75 C25.2@3530.47,4810 ; v1@3503.73,4843.25 3530.47,4870 C24.2@3531.42,4870 ; v1(3527.61,5222.35) C19.2@3523.48,5218.22 ; R37.1@3529.42,4470 3529.42,4468.95 3500.24,4439.76 v1(3500.24,4438.37) 3502.1,4438.37 3530.47,4410 C27.2@3531.42,4410 ; C19.2@3530.47,5210 3522.86,5217.61 C19.2@3523.48,5218.22 ; R24.1@3530.47,5270 3523.48,5263 C19.2@3523.48,5218.22 ; C26.2@3531.42,4750 3530.47,4750 3503.73,4776.75 3498.25,4776.75 v1(3495,4780) 3498.25,4783.25 3503.73,4783.25 C25.2@3530.47,4810 ; C25.2@3531.42,4810 C25.2@3530.47,4810 ; R49.1@3534.42,3670 3534.42,3668.95 3503.85,3638.37 v1(3500.24,3638.37) 3503.49,3635.12 3510.35,3635.12 3535.47,3610 C32.2@3536.42,3610 ; U11.11@3683.78,3565 3684.5,3564.28 3710.03,3564.28 3729.05,3545.26 v1(3731.32,3545.26) ; U10.11@3683.78,4365 3684.5,4364.28 3710.03,4364.28 3729.05,4345.26 v1(3731.32,4345.26) ; U8.11@3683.78,5165 3684.5,5164.28 3710.03,5164.28 3729.05,5145.26 v1(3731.32,5145.26) ; v1(3690,4795) 3691.3,4793.7 3691.3,4758.15 U9.2@3692.6,4756.85 ; U8.3@3905.5,5138.69 U8.3@3906.22,5139.41 U8.2@3906.22,5113.82 3941.18,5113.82 v1(3955,5100) 3991.42,5100 C23.2@4001.42,5090 ; U11.3@3906.22,3539.41 U11.2@3906.22,3513.82 3941.18,3513.82 3952.84,3502.16 v1(3956.08,3502.16) ; U10.3@3906.22,4339.41 U10.2@3906.22,4313.82 3941.18,4313.82 v1(3955,4300) 3991.42,4300 C31.2@4001.42,4290 ; v1@3955,3500 3991.42,3500 C36.2@4001.42,3490 ; v1(3957.56,5178.54) 3960.81,5181.8 3972.27,5181.8 4000.47,5210 C20.2@4001.42,5210 ; v1(3957.78,3578.76) 3961.03,3582.02 3972.49,3582.02 4000.47,3610 C33.2@4001.42,3610 ; v1(3957.78,4378.76) 3961.03,4382.02 3972.49,4382.02 4000.47,4410 C28.2@4001.42,4410 ; C34.2@4058.58,3550 v1(4095,3550) ; C29.2@4058.58,4350 v1(4095,4350) ; C21.2@4058.58,5150 v1(4095,5150)
  Bottom Layer w10: v1(890,1035) 864.19,1035 C85.2@844.19,1055 864.19,1075 v1(890,1075) ; v1(2427.97,4568.63) 2432.57,4568.63 2436.28,4564.92 2452.53,4564.92 C81.2@2467.45,4550 ; v1(2430,4720) 2434.57,4720 2464.57,4690 C78.2@2467.45,4690 ; v1(2430,5635) 2433.25,5638.25 2438.73,5638.25 2470.47,5670 C68.2@2471.42,5670 ; v1(2433.15,5491.98) 2433.15,5492.68 2476.8,5536.33 C69.2@2477.76,5536.33 ; v1(2433.97,4860) 2437.22,4856.75 2443.73,4856.75 2470.47,4830 C77.2@2471.42,4830 ; v1(2433.97,5910) 2433.97,5913.5 2470.47,5950 C65.2@2471.42,5950 ; v1(2433.97,7660) 2433.97,7663.5 2470.47,7700 C62.2@2471.42,7700 ; v1@2434.98,5353.55 2456.61,5375.19 2456.61,5376.14 2470.47,5390 C74.2@2471.42,5390 ; v1(2456,4438.54) 2456,4421.45 C84.2@2467.45,4410 ; C76.2@2471.42,4970 2470.47,4970 2443.73,4996.75 2437.22,4996.75 v1(2433.97,5000) 2433.97,5003.5 2470.47,5040 C75.2@2471.42,5040 ; C67.2@2471.42,5810 2470.47,5810 2443.73,5836.75 2437.22,5836.75 v1(2433.97,5840) 2433.97,5843.5 2470.47,5880 C66.2@2471.42,5880 ; C64.2@2471.42,6230 2470.47,6230 2443.73,6256.75 2437.22,6256.75 v1(2433.97,6260) 2433.97,6263.5 2470.47,6300 C63.2@2471.42,6300 ; C83.2@2918.58,4445 2932.44,4458.86 2948.86,4458.86 v1(2970,4480) 2966.75,4483.25 2957.18,4483.25 2925.43,4515 C82.2@2922.55,4515 ; C80.2@2918.58,4585 2918.58,4588.58 2925,4595 2929.53,4595 2951.27,4616.75 2966.75,4616.75 v1(2970,4620) 2966.75,4623.25 2957.18,4623.25 2925.43,4655 C79.2@2922.55,4655 ; C73.2@3050,5426.42 3050,5425.47 3076.75,5398.73 3076.75,5385.59 v1(3080,5382.34) 3083.25,5385.59 3083.25,5398.73 3110,5425.47 C72.2@3110,5426.42 ; C71.2@3170,5426.42 3183.86,5412.56 3183.86,5393.57 3193.22,5384.21 v1(3193.22,5379.61) 3196.47,5382.87 3196.47,5391.94 3230,5425.47 C70.2@3230,5426.42
  other v1: 1410,1004.17 275,1035 330,1035 380,1035 1410,1039.17 305,1070 355,1070 1410,1074.17 275,1105 330,1105 380,1105 1900,1110 1940,1110 1880,1140 1920,1140 2000,1220 2000,1260 2434.94,5353.55
GND_ISO: C60.2 C61.2 J12.3 J12.5 J12.10 J12.11 U18.4 U19.5 | length 119.5
  Top Layer w10: v1(1770,545) 1766.75,548.25 1756.27,548.25 1725,579.53 1725,580.47 1756.27,611.75 1766.75,611.75 v1(1770,615)
  other v1: 1425.57,639.43 1425.57,674.43 1990,690 2030,690 2070,690 1425.57,709.43 2010,725 2050,725 1990,760 2030,760 2070,760
GPIO_34: C68.1 R88.2 U1.86 | length 312.3
  Top Layer w10: v1(2595,5810) 2596.65,5808.35 2656.02,5808.35 U1.86@2657.68,5806.69
  Bottom Layer w10: R88.2@2528.62,5600 C68.1@2528.58,5670 C68.1@2528.58,5670 2528.58,5703.69 2534.43,5709.54 2552.66,5709.54 2572.2,5729.09 2572.2,5787.2 v1(2595,5810)
GPIO_39: C67.1 R87.2 U1.88 | length 211
  Top Layer w10: v1(2567.35,5837.35) 2569.09,5839.09 2656.77,5839.09 U1.88@2657.68,5838.19
  Bottom Layer w10: R87.2@2528.62,5740 2528.62,5809.09 2556.27,5836.75 2566.75,5836.75 v1(2567.35,5837.35)
I_DC: C78.1 R93.2 U1.18 | length 205.5
  Top Layer w10: v1(2605,4620) 2609.6,4620 2616.1,4613.5 2654.02,4613.5 U1.18@2657.68,4609.84
  Bottom Layer w10: C78.1@2532.55,4690 2532.55,4623.93 cw(c2528.62,4623.93) R93.2@2528.62,4620 v1(2605,4620)
I_DC_N: J5.7 R26.2 R27.1 | length 650.9
  Top Layer w10: R27.1@4189.63,5150 4195.58,5155.95 R26.2@4195.58,5210 4231.72,5210 4306.72,5135 4645.21,5135 4691.38,5181.17 4691.38,5211.38 J5.7@4700,5220
I_DC_P: J5.8 R23.1 R26.1 | length 583.3
  Top Layer w10: R26.1@4134.42,5210 4134.42,5211.05 4160.47,5237.1 4163.35,5237.1 4177.8,5251.55 4177.8,5258.17 R23.1@4189.63,5270 4189.63,5269.07 4201.46,5257.24 4212.76,5257.24 4315,5155 4602.92,5155 4627.76,5179.84 J5.8@4629.92,5179.84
